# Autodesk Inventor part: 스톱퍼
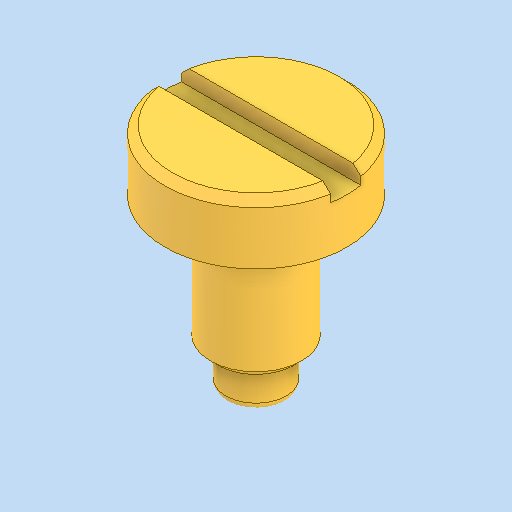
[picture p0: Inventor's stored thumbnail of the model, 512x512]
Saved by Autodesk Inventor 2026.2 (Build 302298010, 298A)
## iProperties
Created: 2026-08
Part Number: 스톱퍼
Material: 스테인리스강
Document SubType Name: Modeling
Designer: PC2-02
Density: 8.08 g/cm^3
Appearance: 기본값
Author: jhkim
Sending System: Autodesk Inventor 2027
Preprocessor: ST-DEVELOPER v20.1
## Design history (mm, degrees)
feature "솔리드1"
node "솔리드2"
